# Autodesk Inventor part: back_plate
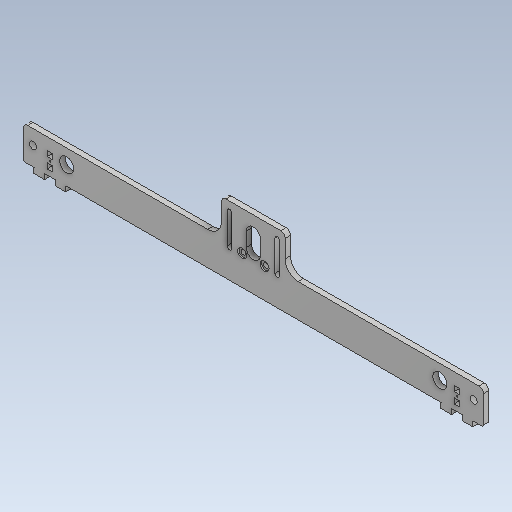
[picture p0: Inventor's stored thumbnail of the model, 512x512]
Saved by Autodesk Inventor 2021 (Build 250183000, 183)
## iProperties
Created: 2026-10
Part Number: back_plate
Material: Steel
Document SubType Name: Modeling
Designer: hp
Density: 7.85 g/cm^3
Appearance: Default
Author: hp
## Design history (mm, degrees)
feature "Body1"
body "Solid1"
